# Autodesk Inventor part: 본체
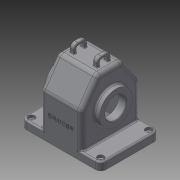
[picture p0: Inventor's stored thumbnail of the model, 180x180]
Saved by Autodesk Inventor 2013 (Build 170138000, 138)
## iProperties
Created: 2016-12
Part Number: 본체
Material: 알루미늄 6061
Document SubType Name: Modeling
Designer: Administrator
Density: 2.71 g/cm^3
Mass: 1110.04 g
Surface Area: 1156.35 cm^2
Volume: 409.61 cm^3
Author: Administrator
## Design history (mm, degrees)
sketch "스케치1"
  geometry: L1 (75, -55)-(-75, -55); L2 (-75, -55)-(-75, 55); L3 (-75, 55)-(75, 55); L4 (75, 55)-(75, -55); L5 (75, -55)-(-75, 55); L6 (-75, -55)-(75, 55); 1 further point
  constraints: 12 end point, 2 midpoint, 2 parallel, 1 horizontal, 1 perpendicular
  dimensions: "d0" = 150 distance of L2.end L3.end; "d1" = 110 distance of L1.end L2.end
extrude "돌출1" new body sketch "스케치1" distance "d2" = 15; taper "d3" = 0 deg
sketch "스케치2"
  geometry: L1 (-38.5, 55)-(38.5, 55); L2 (38.5, 55)-(38.5, -55); L3 (38.5, -55)-(-38.5, -55); L4 (-38.5, -55)-(-38.5, 55); L5 (-38.5, 55)-(38.5, -55); L6 (38.5, 55)-(-38.5, -55); 1 further point
  constraints: 12 end point, 2 midpoint, 2 parallel, 1 horizontal, 1 perpendicular
  dimensions: "d4" = 77 distance of L2.end L3.end; "d5" = 110 distance of L1.end L2.end
extrude "돌출2" join sketch "스케치2" distance "d6" = 110; taper "d7" = 0 deg
chamfer "모따기1" distance "d8" = 45; stored, may be unused: second distance "d9" = 2, angle "d10" = 35 deg
chamfer "모따기2" distance "d11" = 45; stored, may be unused: second distance "d12" = 2, angle "d13" = 35 deg
sketch "스케치3"
  geometry: 1 further point
fillet "모깎기1" dims "d14" = 10
sketch "스케치4"
  geometry: L1 (55, 15)-(55, 76.847) reference; L2 (-55, 15)-(55, 15) reference; L3 (-55, 15)-(-55, 76.847) reference; L4 (-26.477, 120.736)-(-53.192, 82.583) reference; L5 (18.285, 125)-(-18.285, 125) reference; L6 (53.192, 82.583)-(26.477, 120.736) reference; L7 (-50, 76.847)-(-50, 0); L8 (50, 0)-(50, 76.847); L9 (49.096, 79.715)-(22.381, 117.868); L10 (18.285, 120)-(-18.285, 120); L11 (-22.381, 117.868)-(-49.096, 79.715); L12 (-50, 0)-(50, 0); L13 (-55, 0)-(55, 0) reference; A1 r 10 centre (45, 76.847) between (55, 76.847) and (53.192, 82.583) reference; A2 r 10 centre (-45, 76.847) between (-53.192, 82.583) and (-55, 76.847) reference; A3 r 10 centre (-18.285, 115) between (-18.285, 125) and (-26.477, 120.736) reference; A4 r 10 centre (18.285, 115) between (26.477, 120.736) and (18.285, 125) reference; A5 r 5 centre (-45, 76.847) between (-49.096, 79.715) and (-50, 76.847); A6 r 5 centre (45, 76.847) between (50, 76.847) and (49.096, 79.715); A7 r 5 centre (18.285, 115) between (22.381, 117.868) and (18.285, 120); A8 r 5 centre (-18.285, 115) between (-18.285, 120) and (-22.381, 117.868); 1 further point
  constraints: 12 end point, 8 point on circle, 4 centre point, 1 collinear, 1 parallel, 7 other
  dimensions: "d15" = 5 distance between parallel lines of L11 L4; "d16" = 5 distance between parallel lines of L7 L3
extrude "돌출3" cut sketch "스케치4" stored distance "d17" = 67; taper "d18" = 0 deg
fillet "모깎기2" dims "d19" = 8
fillet "모깎기3" dims "d20" = 3
fillet "모깎기4" dims "d21" = 10
sketch "스케치5"
  geometry: A1 r 10 centre (-65, 45) between (-65, 55) and (-75, 45) reference; A2 r 10 centre (-65, -45) between (-75, -45) and (-65, -55) reference; 1 further point
sketch "스케치6"
  geometry: A1 r 10 centre (65, 45) between (75, 45) and (65, 55) reference; A2 r 10 centre (65, -45) between (65, -55) and (75, -45) reference; 1 further point
hole "구멍1" sketch "스케치5" diameter "d22" = 5; stored, may be unused: countersink angle "d26" = 90 deg, drill point angle "d28" = 118 deg; dims "d23" = 6, "d24" = 12, "d25" = 5, "d27" = 8
hole "구멍2" sketch "스케치6" diameter "d29" = 5; stored, may be unused: countersink angle "d33" = 90 deg, drill point angle "d35" = 118 deg; dims "d30" = 6, "d31" = 12, "d32" = 5, "d34" = 8
node "작업 평면1"
sketch "스케치7"
  geometry: L1 (-12.5, 140)-(12.5, 140); L2 (12.5, 140)-(12.5, 125); L3 (12.5, 125)-(-12.5, 125); L4 (-12.5, 125)-(-12.5, 140); L5 (47, 0)-(-47, 0) reference; L6 (-18.285, 125)-(18.285, 125) reference; L7 (-7.5, 135)-(7.5, 135); L8 (7.5, 135)-(7.5, 125); L9 (7.5, 125)-(-7.5, 125); L10 (-7.5, 125)-(-7.5, 135); 5 further points
  constraints: 16 end point, 4 midpoint, 4 parallel, 2 collinear, 2 horizontal, 2 perpendicular, 1 coincident, 1 vertical alignment
  dimensions: "d37" = 140 distance between parallel lines of L1 L5; "d38" = 25 distance of L1.start L1.end; "d39" = 15 distance of L7.start L7.end; "d40" = 5 distance between parallel lines of L1 L7
extrude "돌출4" join sketch "스케치7" distance "d41" = 8; taper "d42" = 0 deg
fillet "모깎기5" dims "d43" = 8
fillet "모깎기6" dims "d44" = 3
fillet "모깎기7" dims "d45" = 1
fillet "모깎기8" dims "d46" = 1
fillet "모깎기9" dims "d47" = 3
fillet "모깎기10" dims "d48" = 3
sketch "스케치8"
  geometry: L1 (117, 63.285)-(117, -26.715) reference; C1 r 31 at (52, 18.285); 2 further points
  constraints: 1 centre point, 1 horizontal alignment, 1 midpoint
  dimensions: "d49" = 62 diameter of C1; "d50" = 65 distance from line of C1.centre L1
extrude "돌출5" join sketch "스케치8" distance "d51" = 10; taper "d52" = 0 deg
sketch "스케치9"
  geometry: L1 (33.5, 106)-(19.5, 92); L2 (19.5, 92)-(19.5, 65); L3 (33.5, 65)-(33.5, 106); L4 (33.5, 65)-(19.5, 65); L5 (-30.5, 0)-(30.5, 0) reference; L6 (33.5, 116.147)-(33.5, 77.994) reference; 1 further point
  constraints: 8 end point, 1 collinear, 1 horizontal, 1 parallel, 1 vertical
  dimensions: "d53" = 65 distance between parallel lines of L4 L5; "d54" = 54 diameter of L1.end L4; "d55" = 45 deg angle of L1 L2; "d56" = 14 distance of L3.start L2.end
revolve "회전1" sketch "스케치9" stored, may be unused: angle "d57" = 90 deg
sketch "스케치10"
  geometry: C1 r 31 at (-52, 18.285) reference; C2 r 37.5 at (-52, 18.285); 1 further point
  constraints: 1 centre point, 1 coincident
  dimensions: "d58" = 75 diameter of C2
extrude "돌출6" join sketch "스케치10" distance "d59" = 10; taper "d60" = 0 deg
hole "구멍3" diameter "d63" = 40; stored, may be unused: countersink angle "d67" = 90 deg, drill point angle "d69" = 118 deg; dims "d61" = 10, "d62" = 10, "d64" = 6, "d65" = 12, "d66" = 5, "d68" = 8
sketch "스케치11"
  geometry: C1 r 20 at (0, 0) reference; 2 further points
  constraints: 1 horizontal alignment
  dimensions: "d70" = 29 distance of C1.centre point (29, 0)
hole "구멍4" sketch "스케치11" at (29, 0) diameter "d71" = 2.459; stored, may be unused: countersink angle "d75" = 90 deg, drill point angle "d77" = 118 deg; dims "d72" = 6, "d73" = 12, "d74" = 5, "d76" = 8
sketch "스케치12"
  geometry: C1 r 20 at (0, 0) reference; 2 further points
  constraints: 1 horizontal alignment
  dimensions: "d81" = 26 distance of C1.centre point (-26, 0)
hole "구멍5" sketch "스케치12" at (-26, 0) diameter "d82" = 2.459; stored, may be unused: countersink angle "d86" = 90 deg, drill point angle "d88" = 118 deg; dims "d83" = 6, "d84" = 12, "d85" = 5, "d87" = 8
fillet "모깎기11" dims "d92" = 3
chamfer "모따기3" distance "d93" = 1; stored, may be unused: second distance "d94" = 2, angle "d95" = 35 deg
sketch "스케치13"
  geometry: L1 (5.369, -28.302)-(55.631, -28.302); L2 (55.631, -28.302)-(55.631, -35.392); L3 (55.631, -35.392)-(5.369, -35.392); L4 (5.369, -35.392)-(5.369, -28.302); L5 (5.369, -31.847)-(55.631, -31.847); L6 (30.5, -28.302)-(30.5, -31.847); L7 (30.5, -76.847)-(30.5, -31.847); L8 (-8, 0)-(-8, -58.847) reference
  constraints: 6 end point, 4 midpoint, 1 collinear, 1 vertical, 2 other
  dimensions: "d96" = 45 distance of L7.start L7.end; "d97" = 38.5 distance between parallel lines of L6 L8
feature "엠보싱1" sketch "스케치13" dims "d98" = 0.5, "d99" = 0
fillet "모깎기12" dims "d100" = 3
node "솔리드1"
mirror "대칭1"
pattern_circular "원형 패턴1" dims angle "d79" = 360 deg
pattern_circular "원형 패턴2" dims angle "d90" = 360 deg
node "투영된 루프1"
other parameters: "d36" = 18
